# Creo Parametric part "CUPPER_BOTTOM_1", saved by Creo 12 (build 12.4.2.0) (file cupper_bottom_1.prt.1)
Units: Custom; MM, KILOGRAM, SECS

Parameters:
  PTC_WM_ITERATION = "0"
  PTC_WM_VERSION = "-.0"
  PTC_WM_LIFECYCLE_STATE = "In Work"
  PTC_WM_LIFECYCLE = "MO_CADDocument"
  PTC_WM_CREATED_BY = "Maximilian Roepper (Z0017RMS: MO)"
  PTC_WM_CREATED_ON = "18-Sep-26 11:36:42 AM"
  PTC_WM_MODIFIED_BY = "Maximilian Roepper (Z0017RMS: MO)"
  PTC_WM_MODIFIED_ON = "18-Sep-26 11:36:46 AM"
  PDMLINKNUMBER = "PDM000071455176"
  PTC_WM_NAME = "cupper_bottom_1.prt"
  PTC_WM_NUMBER = "PDM000071455176"

Other parameters: WEIGHT, WEIGHT_FACTOR, WEIGHT_ADD, _MASS_TEMP, _DIFF_TEMP, MC_ERRORS, SUPPLIER

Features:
  1. coordinate system
  2. datum plane "PRT_YZ"
  3. datum plane "PRT_XY"
  4. datum plane "PRT_XZ"
  5. coordinate system
  6. datum axis
  7. datum axis
  8. datum axis
  9. coordinate system
  10. imported feature
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
Other named items: PRT, SIEMENS_MO, DRW_VIEW_ORG, PRT_X, PRT_Y, PRT_Z, CS0, ROUGH_GROB

Layers: 00_STD_CSYS-KSYS, 01_STD_PLANES-EBENEN, 02_STD_AXES-ACHSEN, 03_STD_CSYS-KSYS, 24_IMPORT_FEAT-IMPORT_KE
